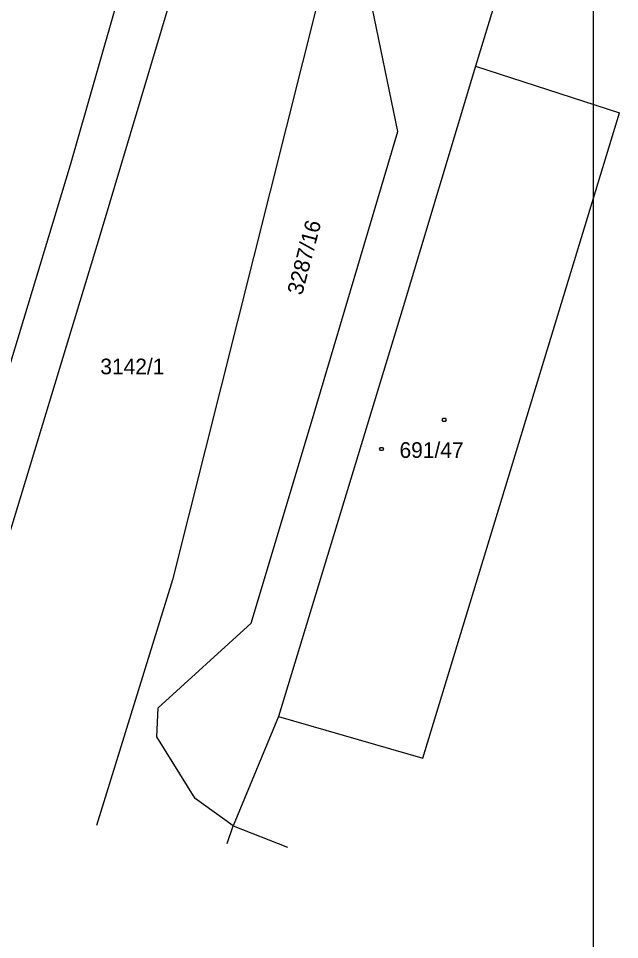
# Model space of a CAD drawing. Extents: x -888468 to -888310, y -1023047 to -1022832.
# Drawn here: x -888340.97 to -888312.21, y -1022961.46 to -1022917.38 of the extents above; entities that cross this region are included whole.
import ezdxf

# ---------------------------------------------------------------- set-up
doc = ezdxf.new("R2010")
doc.units = 0
for name, color, linetype in [('Formát', 7, 'Continuous'), ('Implicitní', 7, 'Continuous'), ('KN stav', 7, 'Continuous')]:
    doc.layers.add(name, color=color, linetype=linetype)

# ---------------------------------------------------------------- blocks, each defined once
blk = doc.blocks.new('402')
at = {"layer": 'Implicitní'}
blk.add_lwpolyline([(0.9, 1.5), (1.8, 0), (0.9, -1.5), (-0.9, -1.5), (-1.8, 0), (-0.9, 1.5), (0.9, 1.5)], dxfattribs=at)

msp = doc.modelspace()

# ---------------------------------------------------------------- linework, layer by layer
at = {"layer": 'Formát'}
msp.add_lwpolyline([(-888461.961, -1022835.294), (-888461.961, -1023045.294), (-888313.461, -1023045.294), (-888313.461, -1022835.294)], close=True, dxfattribs=at)
at = {"layer": 'KN stav'}
for p, q in [((-888329.903, -1022894.294), (-888338.503, -1022924.408)), ((-888337.052, -1022927.708), (-888330.324, -1022905.123)), ((-888316.854, -1022912.291), (-888319.107, -1022919.666)), ((-888325.779, -1022913.109), (-888333.605, -1022944.247)), ((-888322.815, -1022922.784), (-888324.18, -1022916.206)), ((-888319.107, -1022919.666), (-888322.61, -1022931.342)), ((-888319.107, -1022919.666), (-888312.213, -1022921.896)), ((-888321.632, -1022952.784), (-888312.213, -1022921.896)), ((-888312.213, -1022921.896), (-888312.213, -1022921.896)), ((-888327.001, -1022936.851), (-888322.815, -1022922.784)), ((-888338.503, -1022924.408), (-888348.103, -1022956.085)), ((-888345.174, -1022954.436), (-888337.052, -1022927.708)), ((-888322.61, -1022931.342), (-888328.526, -1022950.781)), ((-888329.845, -1022946.319), (-888327.001, -1022936.851)), ((-888333.605, -1022944.247), (-888337.239, -1022956.008)), ((-888334.282, -1022950.371), (-888329.845, -1022946.319)), ((-888334.35, -1022951.759), (-888334.282, -1022950.371)), ((-888328.526, -1022950.781), (-888330.698, -1022956.022)), ((-888328.526, -1022950.781), (-888321.632, -1022952.784)), ((-888332.511, -1022954.702), (-888334.35, -1022951.759)), ((-888330.698, -1022956.022), (-888332.511, -1022954.702)), ((-888330.981, -1022956.869), (-888330.698, -1022956.022)), ((-888330.698, -1022956.022), (-888328.098, -1022957.036))]:
    msp.add_line(p, q, dxfattribs=at)

# ---------------------------------------------------------------- block references
at = {"layer": 'KN stav', "xscale": 0.05, "yscale": 0.05000000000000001}
for p in [(-888320.607, -1022936.59), (-888323.603, -1022937.984)]:
    msp.add_blockref('402', p, dxfattribs=at)

# ---------------------------------------------------------------- texts
at = {"layer": 'KN stav'}
msp.add_text('3287/16', height=0.75, rotation=75.222, dxfattribs=at).set_placement((-888327.405, -1022930.657))
for s, p in [('3142/1', (-888337.058, -1022934.408)), ('691/47', (-888322.742, -1022938.408))]:
    msp.add_text(s, height=0.75, dxfattribs=at).set_placement(p)

doc.saveas('drawing.dxf')
